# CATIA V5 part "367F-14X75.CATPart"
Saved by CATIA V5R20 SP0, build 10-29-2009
Part number: 367F-14X75
Definition: NONE
Nomenclature: 367F-14X75
Source: Unknown
Description: 367F-14X75
Bounding box of the stored display mesh (mm): x 0 to 75, y -14 to 14, z -14 to 14
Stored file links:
  C:\Users\Utente\Desktop\IO LAVORO\3D X SITO CF\X SITO\PLASTICA\3D files 367\367F-14X75.CATPart
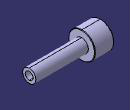
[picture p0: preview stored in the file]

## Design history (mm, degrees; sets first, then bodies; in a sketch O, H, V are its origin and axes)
Body1 "367F-14X75" (main body)
  Solid1: solid without history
